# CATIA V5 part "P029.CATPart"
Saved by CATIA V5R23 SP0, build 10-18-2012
Part number: 05-LICP-T02-E-S07-P029
Definition: Vis CHC M4x27
Publications: "Mating Edge", "Axis"
Bounding box of the stored display mesh (mm): x -27 to 4, y -3.5 to 3.5, z -3.5 to 3.5
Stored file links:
  C:\wamp\www\COURS\CONCEPTION GMP1\TITRE 02-SEMESTRE 2\03-TP7-PRESSE MECANIQUE\eleve\P029.CATPart
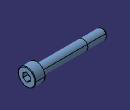
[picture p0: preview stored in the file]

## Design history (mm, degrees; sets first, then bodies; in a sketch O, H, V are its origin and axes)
Parameters
  Material = "St"
  d_dia = 4 mm
  l_nom = 27 mm
  k_head_depth_max = 4 mm
  s_nom = 3 mm
  r_min = 0.2 mm
  ds_max = 4 mm
  e = 3.44 mm
  t_min = 2 mm
  p_pitch = 0.7 mm
  Threading = 8.25 mm
  dk_max = 7 mm
  PartNumber = "ISO 4762 Vis Chc M4x10"
Body1 "PartBody" (main body)
  Sketch1 on yz-plane, origin (0, 0, 0), H (0, 1, 0), V (0, 0, 1)
    circle A1 centre (0, 0) radius 3.5
    radius A1 = 3.5 {= dk_max /2}
  Pad1: profile Sketch1, direction (1, 0, 0), length 4 {= k_head_depth_max}
  Fillet1: radius 0.2 {= r_min}, on edge [face of Pad1 | face of Pad1]
  Body2
    Sketch2 on face of Pad1, origin (4, 0, 0), H (0, 1, 0), V (0, 0, 1)
      point P1 (1.5, -0.866)
      point P2 (1.5, 0.866)
      point P3 (0, 1.7321)
      point P4 (-1.5, 0.866)
      point P5 (-1.5, -0.866)
      point P6 (0, -1.7321)
      point P7 (1.5, 0)
      line L1 (1.5, -0.866) -> (1.5, 0.866)
      line L2 (1.5, 0.866) -> (0, 1.7321)
      line L3 (0, 1.7321) -> (-1.5, 0.866)
      line L4 (-1.5, 0.866) -> (-1.5, -0.866)
      line L5 (-1.5, -0.866) -> (0, -1.7321)
      line L6 (0, -1.7321) -> (1.5, -0.866)
      construction line L7 (0, 0) -> (1.5, 0)
      construction circle A1 centre (0, 0) radius 1.7321
      construction arc A2 centre (-1.5, -0.866) radius 1.7321 from (-1.5, 0.866) to (0, -1.7321) cw
      construction arc A3 centre (1.5, 0.866) radius 1.7321 from (0, 1.7321) to (1.5, -0.866) ccw
      point P8 (-1.5, -0.866)
      point P9 (1.5, 0.866)
      distance L1 L4 = 3 {= s_nom}
      horizontal: L7 H
      coincidence: A1 P1, A1 P2, A1 P3, A1 P4, A1 P5, A1 P6, A2 P4, A2 P6, A2 O, P8 P5, A3 P3, A3 P1, A3 O, P9 P2
      midpoint: P7 L1
    Pad2: profile Sketch2, direction (-1, 0, 0), length 2.9914 {= t_min +(e /3.47)}
    Body3
      Sketch3 on zx-plane, origin (0, 0, 0), H (-1, 0, 0), V (0, 0, 1)
        point P1 (-1.007, 0)
        line L1 (-1.007, 0) -> (-2, 1.72)
        line L2 (-2, 1.72) -> (-4, 1.72)
        line L3 (-4, 1.72) -> (-4, 0)
        axis line L4 (-46.2384, 0) -> (26.3409, 0)
        reference projected line E1 (-4, -6.9227) -> (-4, 6.9227) from edge [face of Pad2 | face of Pad2]
        length L2 = 2 {= t_min}
        angle L1 L4 = 60
        distance L2 L4 = 1.72 {= e /2}
        horizontal: L2 H, L4 H
        perpendicularity: L3 L2
        fix: L4
        coincidence: L3 E1, P1 L4
      Shaft1: profile Sketch3, axis Sketch3.L4, angle 360
    Intersect1: tool Body3
  Remove1: tool Body2
  Sketch4 on xy-plane, origin (0, 0, 0), H (1, 0, 0), V (0, 1, 0)
    line L1 (0, 0) -> (0, 2)
    line L2 (0, 2) -> (-18.75, 2)
    line L3 (-18.75, 2) -> (-18.75, 1.9512)
    line L4 (-18.75, 1.9512) -> (-27, 1.9512)
    line L5 (-27, 1.9512) -> (-27, 0)
    axis line L6 (-192.3446, 0) -> (99.1594, 0)
    distance L5 L1 = 27 {= l_nom}
    distance L3 L5 = 8.25 {= Threading}
    distance L2 L6 = 2 {= ds_max /2}
    distance L4 L6 = 1.9512 {= d_dia /2.05}
    vertical: L1 V, L3 V, L5 V
    horizontal: L2 H, L4 H, L6 H
    fix: L6
  Shaft2: profile Sketch4, axis Sketch4.L6, angle 360
  Fillet2: radius 0.2 {= r_min}, on edge [face of Shaft2 | face of Pad1]
  Chamfer1: length 0.7 {= p_pitch}, angle 45, on edge [face of Shaft2 | face of Shaft2]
